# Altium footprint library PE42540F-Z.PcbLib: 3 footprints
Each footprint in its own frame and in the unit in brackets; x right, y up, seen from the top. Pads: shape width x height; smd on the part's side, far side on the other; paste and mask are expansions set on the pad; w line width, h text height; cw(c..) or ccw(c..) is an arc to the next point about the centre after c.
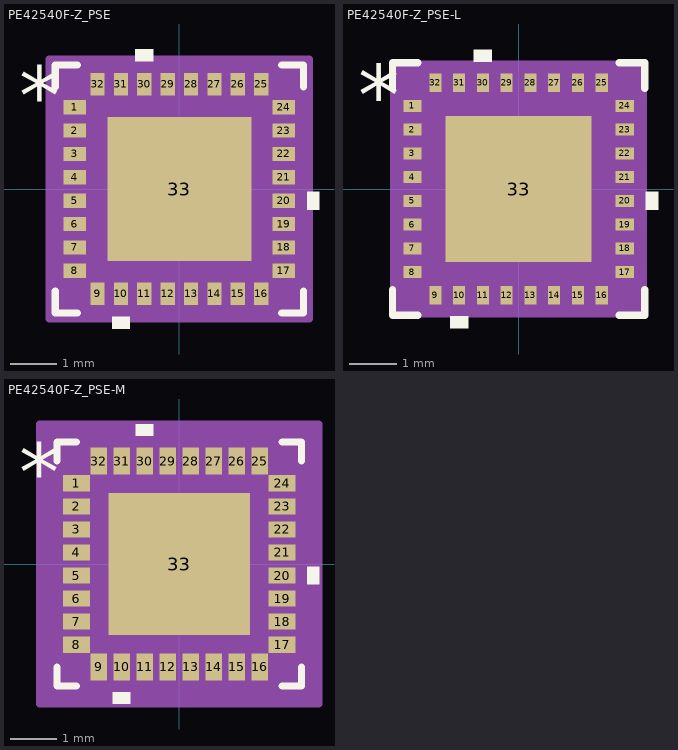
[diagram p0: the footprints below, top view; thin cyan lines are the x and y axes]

## PE42540F-Z_PSE [mil]
pads (33):
  rect 19x12 smd paste+0 mask+0: 1(-88,68.9) 2(-88,49.21) 3(-88,29.53) 4(-88,9.84) 5(-88,-9.84) 6(-88,-29.53) 7(-88,-49.21) 8(-88,-68.9) 17(88,-68.9) 18(88,-49.21) 19(88,-29.53) 20(88,-9.84) 21(88,9.84) 22(88,29.53) 23(88,49.21) 24(88,68.9)
  rect 12x19 smd paste+0 mask+0: 9(-68.9,-88) 10(-49.21,-88) 11(-29.53,-88) 12(-9.84,-88) 13(9.84,-88) 14(29.53,-88) 15(49.21,-88) 16(68.9,-88) 25(68.9,88) 26(49.21,88) 27(29.53,88) 28(9.84,88) 29(-9.84,88) 30(-29.53,88) 31(-49.21,88) 32(-68.9,88)
  rect 121x121 smd paste-60.5 mask+0: 33(0,0)
Top Overlay:
  region: -41.71,-107.5 -56.71,-107.5 -56.71,-117.5 -41.71,-117.5
  region: 107.5,-2.34 117.5,-2.34 117.5,-17.34 107.5,-17.34
  region: -22.03,107.5 -37.03,107.5 -37.03,117.5 -22.03,117.5
  lines w6: -104.5,-85.97 -104.5,-104.5 -85.97,-104.5 ; -104.5,85.97 -104.5,104.5 -85.97,104.5 ; 85.97,-104.5 104.5,-104.5 104.5,-85.97 ; 85.97,104.5 104.5,104.5 104.5,85.97
  text "*" at -135,53.74 h50
Top Paste:
  region: -3.94,56.56 -56.56,56.56 -56.56,3.94 -3.94,3.94
  region: -3.94,-3.94 -56.56,-3.94 -56.56,-56.56 -3.94,-56.56
  region: 56.56,56.56 3.94,56.56 3.94,3.94 56.56,3.94
  region: 56.56,-3.94 3.94,-3.94 3.94,-56.56 56.56,-56.56
Mechanical 13:
  lines w1: -99.5,49.5 -49.5,99.5 ; -99.5,-99.5 99.5,-99.5 ; -99.5,-99.5 -99.5,99.5 ; -99.5,-99.5 -99.5,-99.5 ; -99.5,99.5 99.5,99.5 ; -99.5,99.5 -99.5,99.5 ; 99.5,-99.5 99.5,-99.5 ; 99.5,-99.5 99.5,99.5 ; 99.5,99.5 99.5,99.5 ; -99.5,-74.9 -99.5,-62.9 -97.5,-62.9 -97.5,-74.9 -99.5,-74.9 ; -99.5,-55.21 -99.5,-43.21 -97.5,-43.21 -97.5,-55.21 -99.5,-55.21 ; -99.5,-35.53 -99.5,-23.53 -97.5,-23.53 -97.5,-35.53 -99.5,-35.53 ; -99.5,-15.84 -99.5,-3.84 -97.5,-3.84 -97.5,-15.84 -99.5,-15.84 ; -99.5,3.84 -99.5,15.84 -97.5,15.84 -97.5,3.84 -99.5,3.84 ; -99.5,23.53 -99.5,35.53 -97.5,35.53 -97.5,23.53 -99.5,23.53 ; -99.5,43.21 -99.5,55.21 -97.5,55.21 -97.5,43.21 -99.5,43.21 ; -99.5,62.9 -99.5,74.9 -97.5,74.9 -97.5,62.9 -99.5,62.9 ; -74.9,-99.5 -62.9,-99.5 -62.9,-97.5 -74.9,-97.5 -74.9,-99.5 ; -74.9,97.5 -62.9,97.5 -62.9,99.5 -74.9,99.5 -74.9,97.5 ; -55.21,-99.5 -43.21,-99.5 -43.21,-97.5 -55.21,-97.5 -55.21,-99.5 ; -55.21,97.5 -43.21,97.5 -43.21,99.5 -55.21,99.5 -55.21,97.5 ; -35.53,-99.5 -23.53,-99.5 -23.53,-97.5 -35.53,-97.5 -35.53,-99.5 ; -35.53,97.5 -23.53,97.5 -23.53,99.5 -35.53,99.5 -35.53,97.5 ; -15.84,-99.5 -3.84,-99.5 -3.84,-97.5 -15.84,-97.5 -15.84,-99.5 ; -15.84,97.5 -3.84,97.5 -3.84,99.5 -15.84,99.5 -15.84,97.5 ; 3.84,-99.5 15.84,-99.5 15.84,-97.5 3.84,-97.5 3.84,-99.5 ; 3.84,97.5 15.84,97.5 15.84,99.5 3.84,99.5 3.84,97.5 ; 23.53,-99.5 35.53,-99.5 35.53,-97.5 23.53,-97.5 23.53,-99.5 ; 23.53,97.5 35.53,97.5 35.53,99.5 23.53,99.5 23.53,97.5 ; 43.21,-99.5 55.21,-99.5 55.21,-97.5 43.21,-97.5 43.21,-99.5 ; 43.21,97.5 55.21,97.5 55.21,99.5 43.21,99.5 43.21,97.5 ; 62.9,-99.5 74.9,-99.5 74.9,-97.5 62.9,-97.5 62.9,-99.5 ; 62.9,97.5 74.9,97.5 74.9,99.5 62.9,99.5 62.9,97.5 ; 97.5,-74.9 99.5,-74.9 99.5,-62.9 97.5,-62.9 97.5,-74.9 ; 97.5,-55.21 99.5,-55.21 99.5,-43.21 97.5,-43.21 97.5,-55.21 ; 97.5,-35.53 99.5,-35.53 99.5,-23.53 97.5,-23.53 97.5,-35.53 ; 97.5,-15.84 99.5,-15.84 99.5,-3.84 97.5,-3.84 97.5,-15.84 ; 97.5,3.84 99.5,3.84 99.5,15.84 97.5,15.84 97.5,3.84 ; 97.5,23.53 99.5,23.53 99.5,35.53 97.5,35.53 97.5,23.53 ; 97.5,43.21 99.5,43.21 99.5,55.21 97.5,55.21 97.5,43.21 ; 97.5,62.9 99.5,62.9 99.5,74.9 97.5,74.9 97.5,62.9
  text "*" at -91,53.74 h50
Mechanical 15:
  region: -84.9,-109.5 -109.5,-109.5 -109.5,-84.9 -109.5,84.9 -109.5,109.5 -84.9,109.5 84.9,109.5 109.5,109.5 109.5,84.9 109.5,-84.9 109.5,-109.5 84.9,-109.5
  lines w6: -109.5,-84.9 -109.5,-109.5 -84.9,-109.5 ; -109.5,-84.9 -109.5,-84.9 ; -109.5,-84.9 -109.5,84.9 ; -109.5,84.9 -109.5,84.9 ; -109.5,84.9 -109.5,109.5 -84.9,109.5 ; -84.9,-109.5 84.9,-109.5 ; -84.9,-109.5 -84.9,-109.5 ; -84.9,109.5 -84.9,109.5 ; -84.9,109.5 84.9,109.5 ; 84.9,-109.5 109.5,-109.5 109.5,-84.9 ; 84.9,-109.5 84.9,-109.5 ; 84.9,109.5 84.9,109.5 ; 84.9,109.5 109.5,109.5 109.5,84.9 ; 109.5,-84.9 109.5,84.9 ; 109.5,-84.9 109.5,-84.9 ; 109.5,84.9 109.5,84.9
3D body "PE42540F-Z_PSE.step": height 39.09, standoff 0, extent -99.49,-99.49 99.49,99.49

## PE42540F-Z_PSE-L [mil]
pads (33):
  rect 15x10 smd paste+0 mask+0: 1(-88,68.9) 2(-88,49.21) 3(-88,29.53) 4(-88,9.84) 5(-88,-9.84) 6(-88,-29.53) 7(-88,-49.21) 8(-88,-68.9) 17(88,-68.9) 18(88,-49.21) 19(88,-29.53) 20(88,-9.84) 21(88,9.84) 22(88,29.53) 23(88,49.21) 24(88,68.9)
  rect 10x15 smd paste+0 mask+0: 9(-68.9,-88) 10(-49.21,-88) 11(-29.53,-88) 12(-9.84,-88) 13(9.84,-88) 14(29.53,-88) 15(49.21,-88) 16(68.9,-88) 25(68.9,88) 26(49.21,88) 27(29.53,88) 28(9.84,88) 29(-9.84,88) 30(-29.53,88) 31(-49.21,88) 32(-68.9,88)
  rect 121x121 smd paste-60.5 mask+0: 33(0,0)
Top Overlay:
  region: -41.71,-105.5 -56.71,-105.5 -56.71,-115.5 -41.71,-115.5
  region: 105.5,-2.34 115.5,-2.34 115.5,-17.34 105.5,-17.34
  region: -22.03,105.5 -37.03,105.5 -37.03,115.5 -22.03,115.5
  lines w6: -104.5,-83.42 -104.5,-104.5 -83.42,-104.5 ; -104.5,83.42 -104.5,104.5 -83.42,104.5 ; 83.42,-104.5 104.5,-104.5 104.5,-83.42 ; 83.42,104.5 104.5,104.5 104.5,83.42
  text "*" at -133,53.74 h50
Top Paste:
  region: -3.94,56.56 -56.56,56.56 -56.56,3.94 -3.94,3.94
  region: -3.94,-3.94 -56.56,-3.94 -56.56,-56.56 -3.94,-56.56
  region: 56.56,56.56 3.94,56.56 3.94,3.94 56.56,3.94
  region: 56.56,-3.94 3.94,-3.94 3.94,-56.56 56.56,-56.56
Mechanical 13:
  lines w1: -99.5,49.5 -49.5,99.5 ; -99.5,-99.5 99.5,-99.5 ; -99.5,-99.5 -99.5,99.5 ; -99.5,-99.5 -99.5,-99.5 ; -99.5,99.5 99.5,99.5 ; -99.5,99.5 -99.5,99.5 ; 99.5,-99.5 99.5,-99.5 ; 99.5,-99.5 99.5,99.5 ; 99.5,99.5 99.5,99.5 ; -99.5,-74.9 -99.5,-62.9 -97.5,-62.9 -97.5,-74.9 -99.5,-74.9 ; -99.5,-55.21 -99.5,-43.21 -97.5,-43.21 -97.5,-55.21 -99.5,-55.21 ; -99.5,-35.53 -99.5,-23.53 -97.5,-23.53 -97.5,-35.53 -99.5,-35.53 ; -99.5,-15.84 -99.5,-3.84 -97.5,-3.84 -97.5,-15.84 -99.5,-15.84 ; -99.5,3.84 -99.5,15.84 -97.5,15.84 -97.5,3.84 -99.5,3.84 ; -99.5,23.53 -99.5,35.53 -97.5,35.53 -97.5,23.53 -99.5,23.53 ; -99.5,43.21 -99.5,55.21 -97.5,55.21 -97.5,43.21 -99.5,43.21 ; -99.5,62.9 -99.5,74.9 -97.5,74.9 -97.5,62.9 -99.5,62.9 ; -74.9,-99.5 -62.9,-99.5 -62.9,-97.5 -74.9,-97.5 -74.9,-99.5 ; -74.9,97.5 -62.9,97.5 -62.9,99.5 -74.9,99.5 -74.9,97.5 ; -55.21,-99.5 -43.21,-99.5 -43.21,-97.5 -55.21,-97.5 -55.21,-99.5 ; -55.21,97.5 -43.21,97.5 -43.21,99.5 -55.21,99.5 -55.21,97.5 ; -35.53,-99.5 -23.53,-99.5 -23.53,-97.5 -35.53,-97.5 -35.53,-99.5 ; -35.53,97.5 -23.53,97.5 -23.53,99.5 -35.53,99.5 -35.53,97.5 ; -15.84,-99.5 -3.84,-99.5 -3.84,-97.5 -15.84,-97.5 -15.84,-99.5 ; -15.84,97.5 -3.84,97.5 -3.84,99.5 -15.84,99.5 -15.84,97.5 ; 3.84,-99.5 15.84,-99.5 15.84,-97.5 3.84,-97.5 3.84,-99.5 ; 3.84,97.5 15.84,97.5 15.84,99.5 3.84,99.5 3.84,97.5 ; 23.53,-99.5 35.53,-99.5 35.53,-97.5 23.53,-97.5 23.53,-99.5 ; 23.53,97.5 35.53,97.5 35.53,99.5 23.53,99.5 23.53,97.5 ; 43.21,-99.5 55.21,-99.5 55.21,-97.5 43.21,-97.5 43.21,-99.5 ; 43.21,97.5 55.21,97.5 55.21,99.5 43.21,99.5 43.21,97.5 ; 62.9,-99.5 74.9,-99.5 74.9,-97.5 62.9,-97.5 62.9,-99.5 ; 62.9,97.5 74.9,97.5 74.9,99.5 62.9,99.5 62.9,97.5 ; 97.5,-74.9 99.5,-74.9 99.5,-62.9 97.5,-62.9 97.5,-74.9 ; 97.5,-55.21 99.5,-55.21 99.5,-43.21 97.5,-43.21 97.5,-55.21 ; 97.5,-35.53 99.5,-35.53 99.5,-23.53 97.5,-23.53 97.5,-35.53 ; 97.5,-15.84 99.5,-15.84 99.5,-3.84 97.5,-3.84 97.5,-15.84 ; 97.5,3.84 99.5,3.84 99.5,15.84 97.5,15.84 97.5,3.84 ; 97.5,23.53 99.5,23.53 99.5,35.53 97.5,35.53 97.5,23.53 ; 97.5,43.21 99.5,43.21 99.5,55.21 97.5,55.21 97.5,43.21 ; 97.5,62.9 99.5,62.9 99.5,74.9 97.5,74.9 97.5,62.9
  text "*" at -93,53.74 h50
Mechanical 15:
  region: -77.9,-103.5 -103.5,-103.5 -103.5,-77.9 -103.5,77.9 -103.5,103.5 -77.9,103.5 77.9,103.5 103.5,103.5 103.5,77.9 103.5,-77.9 103.5,-103.5 77.9,-103.5
  lines w6: -103.5,-77.9 -103.5,-103.5 -77.9,-103.5 ; -103.5,-77.9 -103.5,-77.9 ; -103.5,-77.9 -103.5,77.9 ; -103.5,77.9 -103.5,77.9 ; -103.5,77.9 -103.5,103.5 -77.9,103.5 ; -77.9,-103.5 77.9,-103.5 ; -77.9,-103.5 -77.9,-103.5 ; -77.9,103.5 -77.9,103.5 ; -77.9,103.5 77.9,103.5 ; 77.9,-103.5 103.5,-103.5 103.5,-77.9 ; 77.9,-103.5 77.9,-103.5 ; 77.9,103.5 77.9,103.5 ; 77.9,103.5 103.5,103.5 103.5,77.9 ; 103.5,-77.9 103.5,77.9 ; 103.5,-77.9 103.5,-77.9 ; 103.5,77.9 103.5,77.9
3D body "PE42540F-Z_PSE.step": height 39.09, standoff 0, extent -99.49,-99.49 99.49,99.49

## PE42540F-Z_PSE-M [mil]
pads (33):
  rect 23x14 smd paste+0 mask+0: 1(-88,68.9) 2(-88,49.21) 3(-88,29.53) 4(-88,9.84) 5(-88,-9.84) 6(-88,-29.53) 7(-88,-49.21) 8(-88,-68.9) 17(88,-68.9) 18(88,-49.21) 19(88,-29.53) 20(88,-9.84) 21(88,9.84) 22(88,29.53) 23(88,49.21) 24(88,68.9)
  rect 14x23 smd paste+0 mask+0: 9(-68.9,-88) 10(-49.21,-88) 11(-29.53,-88) 12(-9.84,-88) 13(9.84,-88) 14(29.53,-88) 15(49.21,-88) 16(68.9,-88) 25(68.9,88) 26(49.21,88) 27(29.53,88) 28(9.84,88) 29(-9.84,88) 30(-29.53,88) 31(-49.21,88) 32(-68.9,88)
  rect 121x121 smd paste-60.5 mask+0: 33(0,0)
Top Overlay:
  region: -41.71,-109.5 -56.71,-109.5 -56.71,-119.5 -41.71,-119.5
  region: 109.5,-2.34 119.5,-2.34 119.5,-17.34 109.5,-17.34
  region: -22.03,109.5 -37.03,109.5 -37.03,119.5 -22.03,119.5
  lines w6: -104.5,-88.01 -104.5,-104.5 -88.01,-104.5 ; -104.5,88.01 -104.5,104.5 -88.01,104.5 ; 88.01,-104.5 104.5,-104.5 104.5,-88.01 ; 88.01,104.5 104.5,104.5 104.5,88.01
  text "*" at -137,53.74 h50
Top Paste:
  region: -3.94,56.56 -56.56,56.56 -56.56,3.94 -3.94,3.94
  region: -3.94,-3.94 -56.56,-3.94 -56.56,-56.56 -3.94,-56.56
  region: 56.56,56.56 3.94,56.56 3.94,3.94 56.56,3.94
  region: 56.56,-3.94 3.94,-3.94 3.94,-56.56 56.56,-56.56
Mechanical 13:
  lines w1: -99.5,49.5 -49.5,99.5 ; -99.5,-99.5 99.5,-99.5 ; -99.5,-99.5 -99.5,99.5 ; -99.5,-99.5 -99.5,-99.5 ; -99.5,99.5 99.5,99.5 ; -99.5,99.5 -99.5,99.5 ; 99.5,-99.5 99.5,-99.5 ; 99.5,-99.5 99.5,99.5 ; 99.5,99.5 99.5,99.5 ; -99.5,-74.9 -99.5,-62.9 -97.5,-62.9 -97.5,-74.9 -99.5,-74.9 ; -99.5,-55.21 -99.5,-43.21 -97.5,-43.21 -97.5,-55.21 -99.5,-55.21 ; -99.5,-35.53 -99.5,-23.53 -97.5,-23.53 -97.5,-35.53 -99.5,-35.53 ; -99.5,-15.84 -99.5,-3.84 -97.5,-3.84 -97.5,-15.84 -99.5,-15.84 ; -99.5,3.84 -99.5,15.84 -97.5,15.84 -97.5,3.84 -99.5,3.84 ; -99.5,23.53 -99.5,35.53 -97.5,35.53 -97.5,23.53 -99.5,23.53 ; -99.5,43.21 -99.5,55.21 -97.5,55.21 -97.5,43.21 -99.5,43.21 ; -99.5,62.9 -99.5,74.9 -97.5,74.9 -97.5,62.9 -99.5,62.9 ; -74.9,-99.5 -62.9,-99.5 -62.9,-97.5 -74.9,-97.5 -74.9,-99.5 ; -74.9,97.5 -62.9,97.5 -62.9,99.5 -74.9,99.5 -74.9,97.5 ; -55.21,-99.5 -43.21,-99.5 -43.21,-97.5 -55.21,-97.5 -55.21,-99.5 ; -55.21,97.5 -43.21,97.5 -43.21,99.5 -55.21,99.5 -55.21,97.5 ; -35.53,-99.5 -23.53,-99.5 -23.53,-97.5 -35.53,-97.5 -35.53,-99.5 ; -35.53,97.5 -23.53,97.5 -23.53,99.5 -35.53,99.5 -35.53,97.5 ; -15.84,-99.5 -3.84,-99.5 -3.84,-97.5 -15.84,-97.5 -15.84,-99.5 ; -15.84,97.5 -3.84,97.5 -3.84,99.5 -15.84,99.5 -15.84,97.5 ; 3.84,-99.5 15.84,-99.5 15.84,-97.5 3.84,-97.5 3.84,-99.5 ; 3.84,97.5 15.84,97.5 15.84,99.5 3.84,99.5 3.84,97.5 ; 23.53,-99.5 35.53,-99.5 35.53,-97.5 23.53,-97.5 23.53,-99.5 ; 23.53,97.5 35.53,97.5 35.53,99.5 23.53,99.5 23.53,97.5 ; 43.21,-99.5 55.21,-99.5 55.21,-97.5 43.21,-97.5 43.21,-99.5 ; 43.21,97.5 55.21,97.5 55.21,99.5 43.21,99.5 43.21,97.5 ; 62.9,-99.5 74.9,-99.5 74.9,-97.5 62.9,-97.5 62.9,-99.5 ; 62.9,97.5 74.9,97.5 74.9,99.5 62.9,99.5 62.9,97.5 ; 97.5,-74.9 99.5,-74.9 99.5,-62.9 97.5,-62.9 97.5,-74.9 ; 97.5,-55.21 99.5,-55.21 99.5,-43.21 97.5,-43.21 97.5,-55.21 ; 97.5,-35.53 99.5,-35.53 99.5,-23.53 97.5,-23.53 97.5,-35.53 ; 97.5,-15.84 99.5,-15.84 99.5,-3.84 97.5,-3.84 97.5,-15.84 ; 97.5,3.84 99.5,3.84 99.5,15.84 97.5,15.84 97.5,3.84 ; 97.5,23.53 99.5,23.53 99.5,35.53 97.5,35.53 97.5,23.53 ; 97.5,43.21 99.5,43.21 99.5,55.21 97.5,55.21 97.5,43.21 ; 97.5,62.9 99.5,62.9 99.5,74.9 97.5,74.9 97.5,62.9
  text "*" at -89,53.74 h50
Mechanical 15:
  region: -95.9,-119.5 -119.5,-119.5 -119.5,-95.9 -119.5,95.9 -119.5,119.5 -95.9,119.5 95.9,119.5 119.5,119.5 119.5,95.9 119.5,-95.9 119.5,-119.5 95.9,-119.5
  lines w6: -119.5,-95.9 -119.5,-119.5 -95.9,-119.5 ; -119.5,-95.9 -119.5,-95.9 ; -119.5,-95.9 -119.5,95.9 ; -119.5,95.9 -119.5,95.9 ; -119.5,95.9 -119.5,119.5 -95.9,119.5 ; -95.9,-119.5 95.9,-119.5 ; -95.9,-119.5 -95.9,-119.5 ; -95.9,119.5 -95.9,119.5 ; -95.9,119.5 95.9,119.5 ; 95.9,-119.5 119.5,-119.5 119.5,-95.9 ; 95.9,-119.5 95.9,-119.5 ; 95.9,119.5 95.9,119.5 ; 95.9,119.5 119.5,119.5 119.5,95.9 ; 119.5,-95.9 119.5,95.9 ; 119.5,-95.9 119.5,-95.9 ; 119.5,95.9 119.5,95.9
3D body "PE42540F-Z_PSE.step": height 39.09, standoff 0, extent -99.49,-99.49 99.49,99.49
